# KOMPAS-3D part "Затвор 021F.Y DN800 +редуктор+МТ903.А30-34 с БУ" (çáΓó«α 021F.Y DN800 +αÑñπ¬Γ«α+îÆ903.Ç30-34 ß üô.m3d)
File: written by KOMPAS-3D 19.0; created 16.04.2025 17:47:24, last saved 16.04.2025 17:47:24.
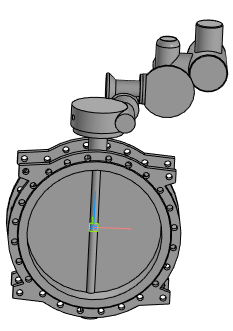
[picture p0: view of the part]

Document properties: Полное имя файла: Затвор 021F.Y DN800 +редуктор+МТ903.А30-34 с БУ.a3d

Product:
- Part/product: Затвор 021F.Y DN800 +редуктор+МТ903.А30-34 с БУ
    Масса: 865.413

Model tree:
1. Операция без истории:1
